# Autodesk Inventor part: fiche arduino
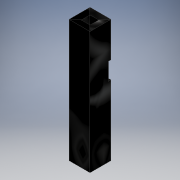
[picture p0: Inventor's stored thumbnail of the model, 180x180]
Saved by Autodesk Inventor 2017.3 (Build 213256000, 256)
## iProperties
Part Number: fiche arduino
Material: Générique
Document SubType Name: Modeling
Designer: ficho
Density: 1 g/cm^3
Appearance: Noir
Author: ficho
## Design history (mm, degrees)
sketch "Esquisse1"
  geometry: L1 (0, 0)-(2.4, 0); L2 (2.4, 0)-(2.4, 2.4); L3 (2.4, 2.4)-(0, 2.4); L4 (0, 2.4)-(0, 0)
  constraints: 8 end point, 2 parallel, 1 horizontal, 1 perpendicular
  dimensions: "d0" = 2.4 distance between parallel lines of L2 L4; "d1" = 2.4 distance between parallel lines of L1 L3
extrude "Extrusion1" new body sketch "Esquisse1" distance "d2" = 14; taper "d3" = 0 deg
sketch "Esquisse2"
  geometry: L1 (0, 0)-(2.4, 0) reference; L2 (2.4, 0)-(2.4, 2.4) reference; L3 (2.4, 2.4)-(0, 2.4) reference; L4 (0, 2.4)-(0, 0) reference; 1 further point
extrude "Extrusion2" cut sketch "Esquisse2" distance "d4" = 0.5; taper "d5" = -85 deg
sketch "Esquisse3"
  geometry: L1 (0, 0)-(-2.4, 0) reference; L2 (0, 2.4)-(0, 0) reference; L3 (-2.4, 2.4)-(0, 2.4) reference; L4 (-2.4, 0)-(-2.4, 2.4) reference; 1 further point
extrude "Extrusion3" cut sketch "Esquisse3" distance "d6" = 0.5; taper "d7" = -85 deg
sketch "Esquisse4"
  geometry: L1 (1.7, 1.7)-(0.7, 1.7); L2 (0.7, 1.7)-(0.7, 0.7); L3 (0.7, 0.7)-(1.7, 0.7); L4 (1.7, 0.7)-(1.7, 1.7); L5 (2.4, 0)-(2.4, 2.4) reference; L6 (2.4, 2.4)-(0, 2.4) reference; 1 further point
  constraints: 8 end point, 2 parallel, 1 horizontal, 1 perpendicular
  dimensions: "d8" = 1 distance between parallel lines of L2 L4; "d9" = 1 distance between parallel lines of L3 L1; "d10" = 0.7 distance between parallel lines of L4 L5; "d11" = 0.7 distance between parallel lines of L6 L1 (= d10)
extrude "Extrusion4" cut sketch "Esquisse4" stored distance "d12" = 0; taper "d13" = 0 deg
sketch "Esquisse5"
  geometry: L1 (-14, 2.4)-(0, 2.4) reference; L2 (-6, 2.4)-(-4, 2.4); L3 (-4, 2.4)-(-4, 2.1); L4 (-4, 2.1)-(-6, 2.1); L5 (-6, 2.1)-(-6, 2.4); L6 (0, 2.4)-(0, 0) reference; 1 further point
  constraints: 8 end point, 2 parallel, 1 horizontal, 1 perpendicular, 1 point on line
  dimensions: "d14" = 0.3 distance between parallel lines of L1 L4; "d15" = 4 distance between parallel lines of L6 L3; "d16" = 2 distance between parallel lines of L3 L5
extrude "Extrusion5" cut sketch "Esquisse5" stored distance "d17" = 0.5; taper "d18" = 0 deg
sketch "Esquisse6"
  geometry: L1 (0, 2)-(2.4, 2) reference; L2 (2.229, 2)-(0.315, 2); L3 (0.315, 2)-(0.315, 0.642); L4 (0.315, 0.642)-(2.229, 0.642); L5 (2.229, 0.642)-(2.229, 2); L6 (2.4, 0)-(0, 0) reference; L7 (1.272, 0.642)-(0.315, 0.642); L8 (0.315, 0.642)-(0.315, 0); L9 (0.315, 0)-(1.272, 0); L10 (1.272, 0)-(1.272, 0.642); 1 further point
  constraints: 16 end point, 4 parallel, 3 point on line, 2 horizontal, 2 perpendicular, 1 midpoint
extrude "Extrusion6" join sketch "Esquisse6" distance "d19" = 0.1; taper "d20" = 0 deg
node "Solide1"
node "Boucle projetée1"
node "Boucle projetée2"
